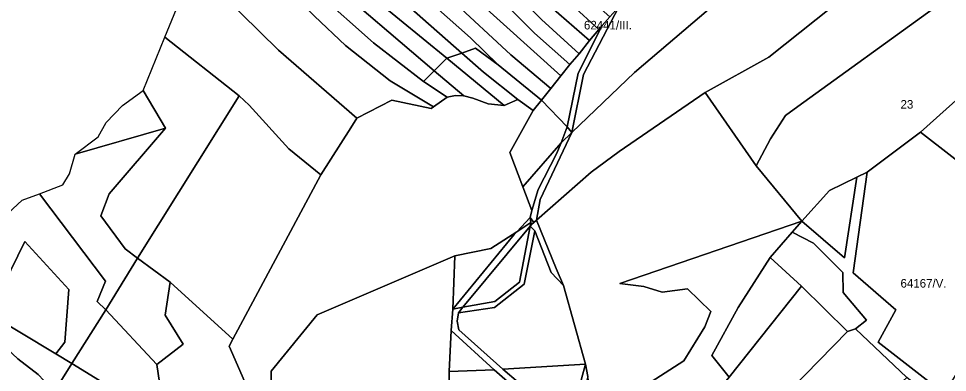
# Model space of a CAD drawing. Extents: x -521261 to -517465, y -1182764 to -1179456.
# Drawn here: x -519763 to -519223, y -1180045 to -1179839 of the extents above; entities that cross this region are included whole.
import ezdxf

# ---------------------------------------------------------------- set-up
doc = ezdxf.new("R2010")
doc.units = 0
for name, color, linetype in [('95560013', 7, 'Continuous'), ('95610013', 7, 'Continuous'), ('95620013', 7, 'Continuous'), ('95640013', 7, 'Continuous'), ('95660013', 7, 'Continuous')]:
    doc.layers.add(name, color=color, linetype=linetype)

msp = doc.modelspace()

# ---------------------------------------------------------------- linework, layer by layer
at = {"layer": '95560013'}
for points in [[(-519548.4, -1179728.82), (-519539.55, -1179723.19), (-519506.36, -1179756.12), (-519460.43, -1179797.99), (-519435.84, -1179823.64), (-519419.43, -1179838.35), (-519423.83, -1179843.37), (-519425.9, -1179845.77), (-519441.61, -1179831.42), (-519468.61, -1179803.29), (-519524.14, -1179753.78)], [(-519556.27, -1179734.13), (-519548.4, -1179728.82), (-519524.14, -1179753.78), (-519468.61, -1179803.29), (-519441.61, -1179831.42), (-519425.9, -1179845.77), (-519431.26, -1179852.28), (-519453.56, -1179832.73), (-519478.58, -1179805.33), (-519527.89, -1179762.65)], [(-519564.43, -1179739.4), (-519556.27, -1179734.13), (-519527.89, -1179762.65), (-519478.58, -1179805.33), (-519453.56, -1179832.73), (-519431.26, -1179852.28), (-519437.26, -1179859.88), (-519459.17, -1179839.89), (-519484.71, -1179814.34), (-519526.65, -1179775.84)], [(-519572.01, -1179744.28), (-519564.43, -1179739.4), (-519526.65, -1179775.84), (-519484.71, -1179814.34), (-519459.17, -1179839.89), (-519437.26, -1179859.88), (-519442.74, -1179866.13), (-519463.3, -1179847.89), (-519477.15, -1179833.93), (-519541.13, -1179775.85)], [(-519583.34, -1179750.61), (-519572.01, -1179744.28), (-519541.13, -1179775.85), (-519477.15, -1179833.93), (-519463.3, -1179847.89), (-519442.74, -1179866.13), (-519447.98, -1179872.79)], [(-519324.74, -1179740.24), (-519318.17, -1179745.69), (-519309.58, -1179753.02), (-519300.17, -1179761.03), (-519293.42, -1179768.94), (-519290.27, -1179772.81), (-519405.1, -1179870.79), (-519441.45, -1179905.77), (-519434.67, -1179872.01), (-519414.29, -1179832.69), (-519408.69, -1179826.66), (-519401.97, -1179819.49), (-519394.73, -1179811.81), (-519386.79, -1179803.12), (-519379.3, -1179795.8), (-519372.32, -1179788.53), (-519365.58, -1179781.36), (-519358.76, -1179774.28), (-519352.56, -1179767.71), (-519345.21, -1179760.33), (-519338.93, -1179754.09), (-519331.97, -1179747.61)], [(-519591.65, -1179757.1), (-519583.34, -1179750.61), (-519447.98, -1179872.79), (-519453.81, -1179880.12), (-519477.04, -1179860.53), (-519511.27, -1179828.64)], [(-519598.98, -1179763.08), (-519591.65, -1179757.1), (-519511.27, -1179828.64), (-519477.04, -1179860.53), (-519453.81, -1179880.12), (-519459.24, -1179886.88), (-519484.38, -1179866.3), (-519500.43, -1179850.73)], [(-519606.08, -1179769.24), (-519598.98, -1179763.08), (-519500.43, -1179850.73), (-519484.38, -1179866.3), (-519497.57, -1179856.71), (-519505.44, -1179859.57), (-519573.52, -1179799.52)], [(-519613.36, -1179775.48), (-519606.08, -1179769.24), (-519573.52, -1179799.52), (-519505.44, -1179859.57), (-519514.27, -1179862.4), (-519555.48, -1179828.46), (-519581.24, -1179805.68)], [(-519619.83, -1179780.93), (-519613.36, -1179775.48), (-519581.24, -1179805.68), (-519555.48, -1179828.46), (-519514.27, -1179862.4), (-519521.66, -1179869.8), (-519586.19, -1179814.48)], [(-519285.96, -1179778.08), (-519286.57, -1179788.67), (-519272.15, -1179802.97), (-519263.31, -1179810.97), (-519326.89, -1179861.96), (-519363.99, -1179882.48), (-519414.1, -1179916.88), (-519430.25, -1179928.79), (-519462.01, -1179956.85), (-519460.01, -1179944.72), (-519441.45, -1179905.77), (-519405.1, -1179870.79), (-519290.27, -1179772.81)], [(-519626.2, -1179787.91), (-519619.83, -1179780.93), (-519586.19, -1179814.48), (-519521.66, -1179869.8), (-519527.72, -1179876.1), (-519556.92, -1179853.62), (-519589.63, -1179824.32)], [(-519414.29, -1179832.69), (-519434.67, -1179872.01), (-519441.45, -1179905.77), (-519444.29, -1179902.47), (-519437.85, -1179871.23), (-519423.83, -1179843.37), (-519419.43, -1179838.35)], [(-519425.9, -1179845.77), (-519423.83, -1179843.37), (-519437.85, -1179871.23), (-519444.29, -1179902.47), (-519459.24, -1179886.88), (-519453.81, -1179880.12), (-519447.98, -1179872.79), (-519442.74, -1179866.13), (-519437.26, -1179859.88), (-519431.26, -1179852.28)]]:
    msp.add_lwpolyline(points, close=True, dxfattribs=at)
at = {"layer": '95610013'}
for points in [[(-519633.09, -1179795.38), (-519626.2, -1179787.91), (-519589.63, -1179824.32), (-519556.92, -1179853.62), (-519527.72, -1179876.1), (-519514.11, -1179885.13), (-519521.99, -1179890.73), (-519547.23, -1179875.75), (-519573.18, -1179855.2), (-519591.12, -1179837.94)], [(-519655.65, -1179814.79), (-519633.09, -1179795.38), (-519591.12, -1179837.94), (-519573.18, -1179855.2), (-519547.23, -1179875.75), (-519521.99, -1179890.73), (-519523.27, -1179891.82), (-519546.18, -1179886.94), (-519566.55, -1179897.34), (-519612.14, -1179857.75)], [(-519670.03, -1179830.37), (-519655.65, -1179814.79), (-519612.14, -1179857.75), (-519566.55, -1179897.34), (-519570.09, -1179903.01), (-519587.53, -1179930.32), (-519606.04, -1179915.21), (-519629.1, -1179889.8), (-519635.04, -1179884.43), (-519678.25, -1179850.34)], [(-519275.76, -1179931.8), (-519283.01, -1179978.66), (-519307.71, -1179957.39), (-519291.7, -1179939.47)], [(-519300.93, -1179970.23), (-519283.91, -1179987.19), (-519283.83, -1179998.93), (-519270.16, -1180015.03), (-519276.5, -1180019.95), (-519281.14, -1180021.48), (-519308, -1179995.12), (-519326.16, -1179978.57), (-519313.5, -1179963.8)], [(-519326.16, -1179978.57), (-519308, -1179995.12), (-519349.98, -1180048.21), (-519360.11, -1180035.57), (-519344.85, -1180007.57)], [(-519808.96, -1179993.71), (-519803.62, -1179997.22), (-519779.85, -1180022.61), (-519763.75, -1180037.47), (-519751.82, -1180046.67), (-519748.53, -1180050.1), (-519775.99, -1180075.06), (-519808.95, -1180039.76), (-519831.1, -1180006.21)], [(-519779.85, -1180022.61), (-519803.62, -1179997.22), (-519741.66, -1180034.52), (-519732.23, -1180040.25), (-519742.51, -1180056.62), (-519748.53, -1180050.1), (-519751.82, -1180046.67), (-519763.75, -1180037.47)], [(-519281.14, -1180021.48), (-519322.25, -1180063.62), (-519346, -1180092.21), (-519374.24, -1180115.97), (-519395.7, -1180129.87), (-519407.49, -1180115.69), (-519366.43, -1180068.13), (-519349.98, -1180048.21), (-519308, -1179995.12)], [(-519281.14, -1180021.48), (-519276.5, -1180019.95), (-519246.76, -1180048.25), (-519280.42, -1180079.34), (-519302.56, -1180095.53), (-519322.25, -1180063.62)], [(-519732.23, -1180040.25), (-519713.64, -1180051.54), (-519730.28, -1180070.6), (-519742.51, -1180056.62)]]:
    msp.add_lwpolyline(points, close=True, dxfattribs=at)
at = {"layer": '95620013'}
for points in [[(-519205.71, -1179818.1), (-519194.43, -1179808.87), (-519165.09, -1179835.93), (-519192.84, -1179864.25), (-519199.62, -1179870.4), (-519238.71, -1179905.52), (-519269.76, -1179928.77), (-519275.76, -1179931.8), (-519291.7, -1179939.47), (-519307.71, -1179957.39), (-519334.26, -1179925.13), (-519326.04, -1179909.41), (-519317.27, -1179895.86), (-519310.04, -1179890.61), (-519231.25, -1179833.5), (-519227.27, -1179831.72), (-519221.39, -1179829.57)], [(-519231.25, -1179833.5), (-519310.04, -1179890.61), (-519317.27, -1179895.86), (-519326.04, -1179909.41), (-519334.26, -1179925.13), (-519363.99, -1179882.48), (-519326.89, -1179861.96), (-519263.31, -1179810.97)], [(-519678.25, -1179850.34), (-519635.04, -1179884.43), (-519694.18, -1179978.78), (-519701.26, -1179973.48), (-519715.46, -1179954.18), (-519710.58, -1179941.34), (-519677.77, -1179903.13), (-519690.81, -1179881.28)], [(-519199.62, -1179870.4), (-519150.51, -1179933.54), (-519152.52, -1179936.19), (-519157.29, -1179942.3), (-519167.62, -1179960.77), (-519238.71, -1179905.52)], [(-519690.81, -1179881.28), (-519677.77, -1179903.13), (-519730.34, -1179918.29), (-519717.08, -1179908.17), (-519712.36, -1179899.96), (-519702.87, -1179890.04)], [(-519629.1, -1179889.8), (-519606.04, -1179915.21), (-519587.53, -1179930.32), (-519638.77, -1180026.02), (-519675.05, -1179992.86), (-519694.18, -1179978.78), (-519635.04, -1179884.43)], [(-519363.99, -1179882.48), (-519334.26, -1179925.13), (-519307.71, -1179957.39), (-519413.72, -1179993.61), (-519399.63, -1179995.3), (-519388.92, -1179998.74), (-519374.34, -1179996.63), (-519360.73, -1180009.86), (-519364.18, -1180018.83), (-519376.5, -1180038.57), (-519427.47, -1180071.49), (-519432.17, -1180047.79), (-519433.63, -1180040.66), (-519446.37, -1179994.71), (-519450.68, -1179984.87), (-519462.01, -1179956.85), (-519430.25, -1179928.79), (-519414.1, -1179916.88)], [(-519459.24, -1179886.88), (-519444.29, -1179902.47), (-519447.82, -1179911.81), (-519470.05, -1179937.4), (-519477.61, -1179917.41), (-519464.04, -1179892.98)], [(-519677.77, -1179903.13), (-519710.58, -1179941.34), (-519715.46, -1179954.18), (-519701.26, -1179973.48), (-519694.18, -1179978.78), (-519712.54, -1180008.89), (-519717.59, -1180004.17), (-519712.82, -1179992.27), (-519751.14, -1179941.36), (-519737.63, -1179936.21), (-519733.58, -1179929.76), (-519730.34, -1179918.29)], [(-519450.42, -1179918.23), (-519461.1, -1179938.97), (-519464.73, -1179951.12), (-519470.05, -1179937.4), (-519447.82, -1179911.81)], [(-519751.14, -1179941.36), (-519712.82, -1179992.27), (-519717.59, -1180004.17), (-519712.54, -1180008.89), (-519732.23, -1180040.25), (-519741.66, -1180034.52), (-519736.36, -1180027.77), (-519734.08, -1179997.11), (-519759.58, -1179969.24), (-519771.94, -1179994.27), (-519784.76, -1179987.32), (-519791.29, -1179994.63), (-519799.94, -1179983.81), (-519808.38, -1179991.55), (-519811.48, -1179988.29), (-519800.15, -1179981.13), (-519761.18, -1179945.18)], [(-519463.15, -1179963), (-519469.29, -1179993.93), (-519486.52, -1180007.56), (-519507.54, -1180010.68), (-519504.86, -1180007.44), (-519486.26, -1180004.17), (-519471.95, -1179992.84), (-519465.79, -1179960.3)], [(-519465.79, -1179960.3), (-519471.95, -1179992.84), (-519486.26, -1180004.17), (-519504.86, -1180007.44)], [(-519464.93, -1179959.26), (-519462.01, -1179956.85), (-519450.68, -1179984.87), (-519446.37, -1179994.71), (-519453.62, -1179987.19), (-519463.15, -1179963), (-519465.79, -1179960.3)], [(-519475.05, -1179965.04), (-519510.74, -1180008.47), (-519509.63, -1179977.46), (-519488.67, -1179973.34), (-519473.6, -1179963.48)], [(-519463.15, -1179963), (-519453.62, -1179987.19), (-519446.37, -1179994.71), (-519433.63, -1180040.66), (-519481.58, -1180043.5), (-519507.22, -1180020.63), (-519508.17, -1180015.61), (-519507.54, -1180010.68), (-519486.52, -1180007.56), (-519469.29, -1179993.93)], [(-519808.38, -1179991.55), (-519799.94, -1179983.81), (-519791.29, -1179994.63), (-519784.76, -1179987.32), (-519771.94, -1179994.27), (-519759.58, -1179969.24), (-519734.08, -1179997.11), (-519736.36, -1180027.77), (-519741.66, -1180034.52), (-519803.62, -1179997.22), (-519807.36, -1179992.82)], [(-519675.05, -1179992.86), (-519678.03, -1180011.99), (-519667.54, -1180028.93), (-519682.86, -1180040.69), (-519712.54, -1180008.89), (-519694.18, -1179978.78)], [(-519509.63, -1179977.46), (-519510.74, -1180008.47), (-519511.79, -1180021.04), (-519512.96, -1180044.92), (-519513.07, -1180055.33), (-519616.46, -1180052.04), (-519616.3, -1180044.63), (-519589.57, -1180011.93)], [(-519678.03, -1180011.99), (-519675.05, -1179992.86), (-519638.77, -1180026.02), (-519640.83, -1180030.17), (-519627.78, -1180059.85), (-519634.46, -1180099.59), (-519675.47, -1180074.7), (-519678.45, -1180070.89), (-519682.86, -1180040.69), (-519667.54, -1180028.93)], [(-519732.23, -1180040.25), (-519712.54, -1180008.89), (-519682.86, -1180040.69), (-519678.45, -1180070.89), (-519712.75, -1180050.51), (-519713.64, -1180051.54)], [(-519486.79, -1180043.85), (-519512.96, -1180044.92), (-519511.79, -1180021.04)], [(-519433.63, -1180040.66), (-519445.23, -1180083.38), (-519463.54, -1180059.07), (-519481.58, -1180043.5)], [(-519433.63, -1180040.66), (-519432.17, -1180047.79), (-519442.84, -1180086.26), (-519445.23, -1180083.38)], [(-519486.79, -1180043.85), (-519466.73, -1180061.32), (-519446.2, -1180087.16), (-519450.45, -1180104.27), (-519476.83, -1180102.39), (-519477.12, -1180090.99), (-519506.79, -1180100.23), (-519513.9, -1180109.18), (-519513.07, -1180055.33), (-519512.96, -1180044.92)]]:
    msp.add_lwpolyline(points, close=True, dxfattribs=at)
msp.add_lwpolyline([(-519627.78, -1180059.85), (-519640.83, -1180030.17), (-519638.77, -1180026.02), (-519587.53, -1179930.32), (-519570.09, -1179903.01), (-519566.55, -1179897.34), (-519546.18, -1179886.94), (-519523.27, -1179891.82), (-519521.99, -1179890.73), (-519514.11, -1179885.13), (-519509.1, -1179884.18), (-519504.39, -1179884.47), (-519499.07, -1179885.79), (-519490.15, -1179888.97), (-519480.93, -1179890.03), (-519472.93, -1179886.51), (-519464.04, -1179892.98), (-519477.61, -1179917.41), (-519470.05, -1179937.4), (-519464.73, -1179951.12), (-519465.85, -1179955.12), (-519473.6, -1179963.48), (-519488.67, -1179973.34), (-519509.63, -1179977.46), (-519589.57, -1180011.93), (-519616.3, -1180044.63), (-519616.46, -1180052.04)], dxfattribs=at)
at = {"layer": '95640013'}
for points in [[(-519497.57, -1179856.71), (-519484.38, -1179866.3), (-519459.24, -1179886.88), (-519464.04, -1179892.98), (-519472.93, -1179886.51), (-519492.83, -1179870.64), (-519505.44, -1179859.57)], [(-519514.27, -1179862.4), (-519480.93, -1179890.03), (-519490.15, -1179888.97), (-519499.07, -1179885.79), (-519504.39, -1179884.47), (-519521.66, -1179869.8)], [(-519505.44, -1179859.57), (-519492.83, -1179870.64), (-519472.93, -1179886.51), (-519480.93, -1179890.03), (-519514.27, -1179862.4)], [(-519521.66, -1179869.8), (-519504.39, -1179884.47), (-519509.1, -1179884.18), (-519514.11, -1179885.13), (-519527.72, -1179876.1)], [(-519447.82, -1179911.81), (-519441.45, -1179905.77), (-519460.01, -1179944.72), (-519462.01, -1179956.85), (-519464.93, -1179959.26), (-519465.79, -1179960.3), (-519465.37, -1179958.1), (-519465.85, -1179955.12), (-519464.73, -1179951.12), (-519461.1, -1179938.97), (-519450.42, -1179918.23)], [(-519441.45, -1179905.77), (-519447.82, -1179911.81), (-519444.29, -1179902.47)], [(-519238.71, -1179905.52), (-519167.62, -1179960.77), (-519188.51, -1179998.17), (-519224.99, -1180057.71), (-519263.35, -1180027.7), (-519253.07, -1180008.97), (-519277.89, -1179987.4), (-519269.76, -1179928.77)], [(-519269.76, -1179928.77), (-519277.89, -1179987.4), (-519253.07, -1180008.97), (-519263.35, -1180027.7), (-519224.99, -1180057.71), (-519228.73, -1180062.96), (-519246.76, -1180048.25), (-519276.5, -1180019.95), (-519270.16, -1180015.03), (-519283.83, -1179998.93), (-519283.91, -1179987.19), (-519300.93, -1179970.23), (-519313.5, -1179963.8), (-519307.71, -1179957.39), (-519283.01, -1179978.66), (-519275.76, -1179931.8)], [(-519465.37, -1179958.1), (-519473.6, -1179963.48), (-519465.85, -1179955.12)], [(-519465.37, -1179958.1), (-519465.79, -1179960.3), (-519504.86, -1180007.44), (-519510.74, -1180008.47), (-519475.05, -1179965.04), (-519473.6, -1179963.48)], [(-519313.5, -1179963.8), (-519326.16, -1179978.57), (-519344.85, -1180007.57), (-519360.11, -1180035.57), (-519349.98, -1180048.21), (-519366.43, -1180068.13), (-519407.49, -1180115.69), (-519414.22, -1180111.31), (-519423.69, -1180093.23), (-519394.55, -1180074.08), (-519427.47, -1180071.49), (-519376.5, -1180038.57), (-519364.18, -1180018.83), (-519360.73, -1180009.86), (-519374.34, -1179996.63), (-519388.92, -1179998.74), (-519399.63, -1179995.3), (-519413.72, -1179993.61), (-519307.71, -1179957.39)], [(-519504.86, -1180007.44), (-519507.54, -1180010.68), (-519508.17, -1180015.61), (-519507.22, -1180020.63), (-519481.58, -1180043.5), (-519463.54, -1180059.07), (-519445.23, -1180083.38), (-519446.2, -1180087.16), (-519466.73, -1180061.32), (-519486.79, -1180043.85), (-519511.79, -1180021.04), (-519510.74, -1180008.47)]]:
    msp.add_lwpolyline(points, close=True, dxfattribs=at)
at = {"layer": '95660013'}
for points in [[(-519800.15, -1179981.13), (-519761.18, -1179945.18), (-519751.14, -1179941.36), (-519737.63, -1179936.21), (-519733.58, -1179929.76), (-519730.34, -1179918.29), (-519717.08, -1179908.17), (-519712.36, -1179899.96), (-519702.87, -1179890.04), (-519690.81, -1179881.28), (-519678.25, -1179850.34), (-519635.04, -1179884.43), (-519629.1, -1179889.8), (-519606.04, -1179915.21), (-519587.53, -1179930.32), (-519570.09, -1179903.01), (-519566.55, -1179897.34), (-519546.18, -1179886.94), (-519523.27, -1179891.82), (-519521.99, -1179890.73), (-519514.11, -1179885.13), (-519509.1, -1179884.18), (-519504.39, -1179884.47), (-519499.07, -1179885.79), (-519490.15, -1179888.97), (-519480.93, -1179890.03), (-519472.93, -1179886.51), (-519464.04, -1179892.98), (-519459.24, -1179886.88), (-519444.29, -1179902.47), (-519447.82, -1179911.81), (-519450.42, -1179918.23), (-519461.1, -1179938.97), (-519464.73, -1179951.12), (-519465.85, -1179955.12), (-519463.56, -1179958.13), (-519462.01, -1179956.85), (-519430.25, -1179928.79), (-519414.1, -1179916.88), (-519363.99, -1179882.48), (-519326.89, -1179861.96), (-519263.31, -1179810.97)], [(-519263.31, -1179810.97), (-519326.89, -1179861.96), (-519363.99, -1179882.48), (-519414.1, -1179916.88), (-519430.25, -1179928.79), (-519462.01, -1179956.85), (-519463.56, -1179958.13), (-519465.85, -1179955.12), (-519464.73, -1179951.12), (-519461.1, -1179938.97), (-519450.42, -1179918.23), (-519447.82, -1179911.81), (-519444.29, -1179902.47), (-519459.24, -1179886.88), (-519464.04, -1179892.98), (-519472.93, -1179886.51), (-519480.93, -1179890.03), (-519490.15, -1179888.97), (-519499.07, -1179885.79), (-519504.39, -1179884.47), (-519509.1, -1179884.18), (-519514.11, -1179885.13), (-519521.99, -1179890.73), (-519523.27, -1179891.82), (-519546.18, -1179886.94), (-519566.55, -1179897.34), (-519570.09, -1179903.01), (-519587.53, -1179930.32), (-519606.04, -1179915.21), (-519629.1, -1179889.8), (-519635.04, -1179884.43), (-519678.25, -1179850.34), (-519670.03, -1179830.37)], [(-519167.62, -1179960.77), (-519238.71, -1179905.52), (-519269.76, -1179928.77), (-519275.76, -1179931.8), (-519291.7, -1179939.47), (-519307.71, -1179957.39), (-519413.72, -1179993.61), (-519399.63, -1179995.3), (-519388.92, -1179998.74), (-519374.34, -1179996.63), (-519360.73, -1180009.86), (-519364.18, -1180018.83), (-519376.5, -1180038.57), (-519427.47, -1180071.49)], [(-519427.47, -1180071.49), (-519376.5, -1180038.57), (-519364.18, -1180018.83), (-519360.73, -1180009.86), (-519374.34, -1179996.63), (-519388.92, -1179998.74), (-519399.63, -1179995.3), (-519413.72, -1179993.61), (-519307.71, -1179957.39), (-519291.7, -1179939.47), (-519275.76, -1179931.8), (-519269.76, -1179928.77), (-519238.71, -1179905.52), (-519167.62, -1179960.77)], [(-519713.64, -1180051.54), (-519732.23, -1180040.25), (-519741.66, -1180034.52), (-519803.62, -1179997.22)], [(-519803.62, -1179997.22), (-519741.66, -1180034.52), (-519732.23, -1180040.25), (-519713.64, -1180051.54)]]:
    msp.add_lwpolyline(points, dxfattribs=at)

# ---------------------------------------------------------------- texts
for s, rotation, p in [('62441/III.', 360, (-519434.49, -1179845.77)), ('23', 0, (-519250.38, -1179891.86)), ('64167/V.', 0, (-519250.4, -1179996.01))]:
    msp.add_text(s, height=5, rotation=rotation, dxfattribs=at).set_placement(p)

doc.saveas('drawing.dxf')
